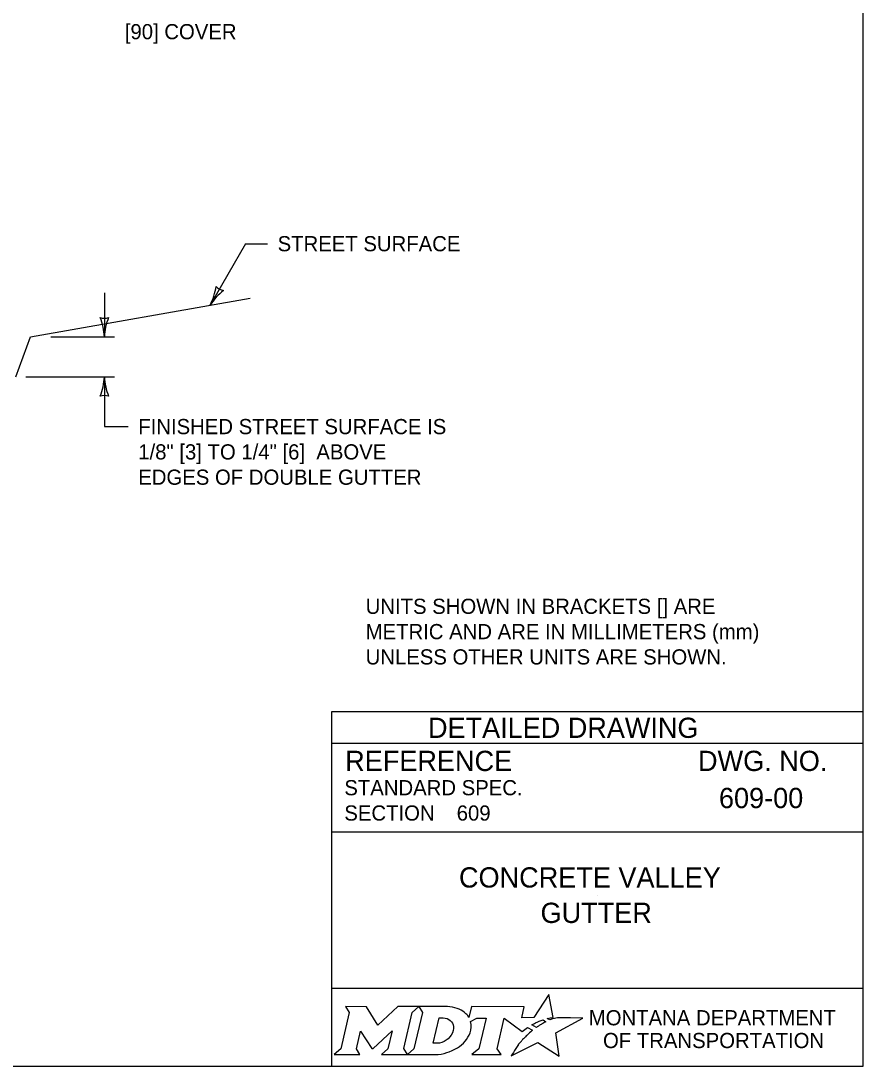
# Model space of a CAD drawing. Extents: x 49991.4 to 50021, y 49987.6 to 50011.4.
# Drawn here: x 50017.61 to 50020.938, y 49999.886 to 50004.018 of the extents above; entities that cross this region are included whole.
import ezdxf

# ---------------------------------------------------------------- set-up
doc = ezdxf.new("R2010")
doc.units = 0
for name, color, linetype in [('Default', 7, 'Continuous'), ('Level 1', 7, 'Continuous'), ('Level 2', 7, 'Continuous'), ('Level 3', 7, 'Continuous'), ('Level 4', 7, 'Continuous')]:
    doc.layers.add(name, color=color, linetype=linetype)

msp = doc.modelspace()

# ---------------------------------------------------------------- linework, layer by layer
at = {"layer": 'Default'}
for points in [[(50019.7003, 50000.0679), (50019.69, 50000.0735), (50019.7016, 50000.0763), (50019.7132, 50000.0783), (50019.6958, 50000.1684), (50019.6363, 50000.0771), (50019.589, 50000.0764), (50019.5993, 50000.1205), (50019.3901, 50000.1206), (50019.38, 50000.0781), (50019.3742, 50000.0864)], [(50018.8933, 50000.1206), (50018.9074, 50000.0972), (50018.8739, 49999.9539), (50018.8482, 49999.9314), (50018.9498, 49999.9314), (50018.9363, 49999.9542), (50018.9525, 50000.0243), (50018.9962, 49999.9553), (50019.0015, 49999.9553), (50019.0766, 50000.0248), (50019.0602, 49999.9537), (50019.0355, 49999.9317), (50019.1371, 49999.9317), (50019.1233, 49999.955), (50019.1565, 50000.0974)], [(50019.1565, 50000.0974), (50019.1818, 50000.1206), (50019.0994, 50000.1206), (50019.0198, 50000.0476), (50018.9753, 50000.1203), (50018.8933, 50000.1206)], [(50019.2954, 50000.1206), (50019.1818, 50000.1206), (50019.1965, 50000.0977), (50019.1626, 49999.9539), (50019.1371, 49999.9317), (50019.2477, 49999.9317)], [(50019.3194, 50000.0339), (50019.3182, 50000.0258), (50019.315, 50000.0165), (50019.3108, 50000.0083), (50019.3052, 50000.0008), (50019.2987, 49999.9939), (50019.2908, 49999.9876), (50019.2825, 49999.9829), (50019.2734, 49999.979), (50019.2643, 49999.9767), (50019.2551, 49999.9758), (50019.2392, 49999.9758), (50019.2628, 50000.0758), (50019.2788, 50000.0758), (50019.2864, 50000.0752), (50019.294, 50000.0733), (50019.3006, 50000.0703), (50019.3067, 50000.0661), (50019.3115, 50000.0611), (50019.3152, 50000.0551), (50019.3179, 50000.0489), (50019.3195, 50000.0415), (50019.3195, 50000.0385), (50019.3194, 50000.0339)], [(50019.3868, 50000.0615), (50019.4114, 50000.0746), (50019.4483, 50000.0746), (50019.4197, 49999.9541), (50019.3922, 49999.9314), (50019.5084, 49999.9314), (50019.4914, 49999.9543), (50019.5196, 50000.0745), (50019.5909, 50000.0228), (50019.612, 50000.0379), (50019.6317, 50000.027)], [(50019.5759, 49999.9711), (50019.5606, 49999.9467), (50019.5559, 49999.9392), (50019.5501, 49999.9306), (50019.5478, 49999.9263), (50019.6531, 49999.9794), (50019.737, 49999.9243), (50019.7239, 50000.017), (50019.8308, 50000.0754), (50019.7815, 50000.0762), (50019.7514, 50000.0766), (50019.7306, 50000.0769), (50019.7238, 50000.0754), (50019.7189, 50000.0742), (50019.7105, 50000.0719), (50019.7003, 50000.0679)], [(50019.6499, 50000.0403), (50019.6475, 50000.0386), (50019.6292, 50000.0482), (50019.6395, 50000.0539), (50019.6436, 50000.0561), (50019.6522, 50000.0601), (50019.6579, 50000.0627), (50019.6658, 50000.0657), (50019.6731, 50000.0684), (50019.6849, 50000.061), (50019.6809, 50000.0589), (50019.6763, 50000.0564), (50019.6721, 50000.0542), (50019.6671, 50000.0513), (50019.6652, 50000.0502), (50019.6625, 50000.0486), (50019.66, 50000.0472), (50019.6577, 50000.0456), (50019.6551, 50000.0438), (50019.6524, 50000.042), (50019.6499, 50000.0403)], [(50019.5898, 49999.9872), (50019.5898, 49999.9872)], [(50019.2934, 49999.939), (50019.3018, 49999.9416), (50019.3148, 49999.947), (50019.3352, 49999.958)]]:
    msp.add_lwpolyline(points, dxfattribs=at)
for centre, radius, start, end in [((50019.3185, 50000.0422), 0.0709, 339.5329, 15.8582), ((50019.2745, 50000.0595), 0.1183, 300.9103, 339.1383)]:
    msp.add_arc(centre, radius, start, end, dxfattribs=at)
for centre, major_axis, ratio, start_param, end_param in [((50019.2933, 50000.0732), (0.0834, -0.0037), 0.568097, 0.61298, 1.570796), ((50019.3489, 50000.0805), (0.0361, -0.0295), 0.469099, 1.225588, 1.570796), ((50019.6206, 50000.0173), (-0.0112, -0.0097), 0.021651, 3.157348, 6.283185), ((50019.5829, 49999.9791), (-0.00694, -0.00806), 0.008222, 0, 3.137361), ((50019.5996, 49999.9974), (-0.0098, -0.0102), 0.016458, 3.141593, 6.279097), ((50019.248, 50000.08), (0, 0.1484), 0.987302, 3.139398, 3.456847)]:
    msp.add_ellipse(centre, major_axis=major_axis, ratio=ratio, start_param=start_param, end_param=end_param, dxfattribs=at)
at = {"layer": 'Level 1'}
for p, q in [((50017.6478, 50002.7686), (50018.5154, 50002.9216)), ((50017.5901, 50002.6101), (50017.6478, 50002.7686))]:
    msp.add_line(p, q, dxfattribs=at)
msp.add_lwpolyline([(50020.9378, 50008.1646), (50009.7374, 50008.1646), (50009.7374, 49999.8856), (50020.9378, 49999.8856)], close=True, dxfattribs=at)
at = {"layer": 'Level 3'}
for p, q in [((50018.4973, 50003.1368), (50018.358, 50002.8938)), ((50018.4973, 50003.1368), (50018.5845, 50003.1368)), ((50017.94, 50002.942), (50017.94, 50002.7686)), ((50017.7278, 50002.7686), (50017.98, 50002.7686)), ((50017.6302, 50002.6101), (50017.98, 50002.6101)), ((50017.94, 50002.6101), (50017.94, 50002.4138)), ((50017.94, 50002.4138), (50018.0338, 50002.4138))]:
    msp.add_line(p, q, dxfattribs=at)
for centre, radius, start, end in [((50018.1504, 50002.9996), 0.233, 333.0038, 352.2536), ((50018.4218, 50003.0051), 0.0548, 222.3153, 258.0376), ((50018.5462, 50002.7754), 0.2223, 127.6325, 147.816), ((50017.94, 50002.8968), 0.0548, 252.1388, 287.8612), ((50017.7073, 50002.7571), 0.233, 2.8273, 22.0772), ((50018.1621, 50002.7594), 0.2223, 157.456, 177.6395), ((50017.7178, 50002.6193), 0.2223, 337.456, 357.6395), ((50018.1727, 50002.6216), 0.233, 182.8273, 202.0772), ((50017.94, 50002.4819), 0.0548, 72.1388, 107.8612)]:
    msp.add_arc(centre, radius, start, end, dxfattribs=at)
at = {"layer": 'Level 4'}
for p, q in [((50020.9378, 50001.2856), (50018.8378, 50001.2856)), ((50018.8378, 50001.2856), (50018.8378, 49999.8856)), ((50020.9378, 50001.1606), (50018.8378, 50001.1606)), ((50020.5739, 50000.9455), (50020.5739, 50000.9455)), ((50019.3321, 50000.8861), (50019.3321, 50000.8861)), ((50020.9378, 50000.8106), (50018.8378, 50000.8106)), ((50019.8878, 50000.5615), (50019.8878, 50000.5615)), ((50020.9378, 50000.1925), (50018.8378, 50000.1925))]:
    msp.add_line(p, q, dxfattribs=at)

# ---------------------------------------------------------------- texts
at = {"layer": 'Default'}
for s, p in [('MONTANA DEPARTMENT', (50019.854, 50000.0468)), ('OF TRANSPORTATION', (50019.9102, 49999.9568))]:
    msp.add_text(s, height=0.06, dxfattribs=at).set_placement(p)
at = {"layer": 'Level 2'}
for s, height, p in [('[90] COVER ', 0.06, (50018.0207, 50003.9451)), ('STREET SURFACE', 0.06, (50018.6245, 50003.1068)), ('FINISHED STREET SURFACE IS', 0.06, (50018.0738, 50002.3838)), ('1/8" [3] TO 1/4" [6]  ABOVE ', 0.06, (50018.0738, 50002.2838)), ('EDGES OF DOUBLE GUTTER', 0.06, (50018.0738, 50002.1838)), ('UNITS SHOWN IN BRACKETS [] ARE ', 0.06, (50018.9723, 50001.6733)), ('METRIC AND ARE IN MILLIMETERS (mm) ', 0.06, (50018.9723, 50001.5733)), ('UNLESS OTHER UNITS ARE SHOWN.', 0.06, (50018.9723, 50001.4733)), ('609-00', 0.08, (50020.3683, 50000.9055)), ('609', 0.06, (50019.3321, 50000.8561)), ('CONCRETE VALLEY', 0.08, (50019.3411, 50000.5915)), ('GUTTER', 0.08, (50019.6634, 50000.4515))]:
    msp.add_text(s, height=height, dxfattribs=at).set_placement(p)
at = {"layer": 'Level 4'}
for s, height, p in [('DETAILED DRAWING', 0.0799, (50019.2188, 50001.1831)), ('REFERENCE', 0.08, (50018.8914, 50001.0522)), ('DWG. NO.', 0.08, (50020.2856, 50001.0522)), ('STANDARD SPEC.', 0.06, (50018.8881, 50000.9562)), ('SECTION', 0.06, (50018.8881, 50000.8562))]:
    msp.add_text(s, height=height, dxfattribs=at).set_placement(p)

doc.saveas('drawing.dxf')
